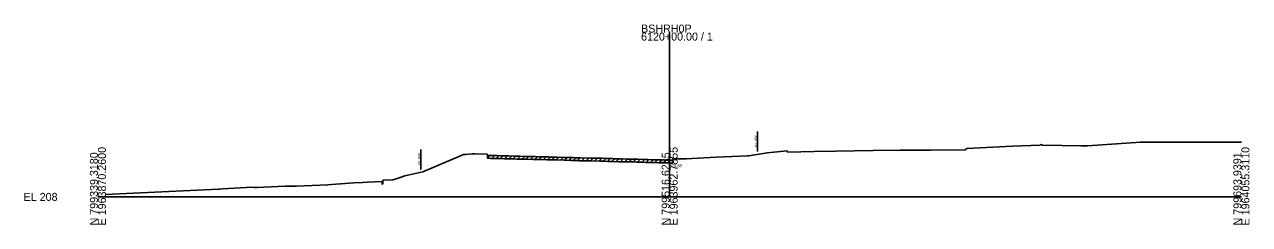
# Model space of a CAD drawing. Extents: x -26 to 1986619, y -10 to 827846.
# Drawn here: x -25.7 to 402.8, y -9.7 to 60.4 of the extents above; entities that cross this region are included whole.
import ezdxf

# ---------------------------------------------------------------- set-up
doc = ezdxf.new("R2010")
doc.units = 0
for name, color, linetype in [('Default', 7, 'Continuous'), ('RD_EX_Road', 7, 'Continuous'), ('RD_PD_ALT5_LnLine', 7, 'Continuous'), ('RD_PD_ALT5_TrvlWay', 7, 'Continuous'), ('RD_PD_PaveDit', 7, 'Continuous'), ('RD_XS_ExRW', 7, 'Continuous')]:
    doc.layers.add(name, color=color, linetype=linetype)

msp = doc.modelspace()

# ---------------------------------------------------------------- linework, layer by layer
at = {"layer": 'RD_EX_Road'}
for p, q in [((200, 0), (200, 57.54)), ((0, 0), (200, 0)), ((200, 0), (400, 0))]:
    msp.add_line(p, q, dxfattribs=at)
at = {"layer": 'RD_PD_ALT5_LnLine'}
msp.add_lwpolyline([(2.52, 0.85), (42.14, 2.71), (42.52, 2.72), (43.56, 2.78), (53.9, 3.34), (54.82, 3.33), (55.64, 3.31), (65.44, 3.69), (67.69, 3.75), (69.43, 3.8), (80.38, 4.27), (81.67, 4.35), (89.54, 4.92), (92.59, 5.07), (94.18, 5.17), (99.6, 5.39), (99.7, 5.84), (103.13, 6.02), (103.99, 6.19), (105.41, 6.7), (107.41, 7.31), (113.65, 8.78), (126.88, 14.39), (127.84, 14.8), (128.62, 14.88), (130.87, 15.1), (131.22, 15.12), (131.86, 15.11), (136.16, 14.95), (136.26, 14.5), (136.51, 14.5), (137.3, 14.48), (138.2, 14.46), (139.6, 14.43), (140.9, 14.39), (142.17, 14.36), (143.19, 14.33), (143.72, 14.32), (145.41, 14.28), (146.53, 14.25), (146.88, 14.24), (147.56, 14.23), (149.29, 14.19), (150.02, 14.16), (152.15, 14.1), (152.96, 14.08), (154.27, 14.05), (154.95, 14.03), (157.12, 13.98), (157.77, 13.97), (158.35, 13.96), (160.59, 13.92), (163.06, 13.83), (163.74, 13.81), (165.39, 13.76), (166.24, 13.73), (167.28, 13.7), (168.09, 13.69), (168.49, 13.67), (168.83, 13.67), (172.29, 13.6), (175.54, 13.53), (176.38, 13.5), (177.56, 13.45), (178.39, 13.42), (179.98, 13.38), (180.37, 13.37), (182.1, 13.32), (183.2, 13.3), (185.41, 13.25), (186.11, 13.24), (187.49, 13.24), (188.32, 13.21), (188.82, 13.2), (190.79, 13.12), (191.62, 13.09), (192.53, 13.07), (194.44, 13.01), (196.19, 12.96), (196.89, 12.94), (197.26, 12.93), (198.24, 12.91), (199.62, 12.88), (200.07, 12.88), (200.93, 12.8), (200.99, 12.9), (201.09, 13.35), (203.54, 13.35), (205.85, 13.33), (211.91, 13.67), (216.42, 13.88), (227.18, 14.32), (227.65, 14.34), (234.12, 15.4), (241.14, 16.12), (241.24, 15.67), (250.5, 15.93), (258.14, 16.01), (271.24, 16.26), (280.48, 16.39), (280.86, 16.39), (281.47, 16.36), (282.1, 16.36), (283.21, 16.36), (284.52, 16.34), (285.81, 16.3), (291.23, 16.37), (303.33, 16.5), (303.92, 16.96), (319.96, 17.81), (329.45, 18.1), (329.69, 18.33), (330.47, 18.13), (343.93, 17.86), (346.13, 17.93), (364.75, 19.12), (400, 19.18)], dxfattribs=at)
at = {"layer": 'RD_PD_PaveDit'}
for p, q in [((136.26, 13.5), (136.26, 14.5)), ((136.26, 13.5), (137.24, 14.49)), ((136.26, 13.5), (136.51, 13.5)), ((136.51, 13.5), (137.3, 13.48)), ((137.3, 13.48), (138.2, 13.46)), ((137.76, 13.47), (138.73, 14.45)), ((138.2, 13.46), (139.6, 13.43)), ((139.26, 13.43), (140.23, 14.41)), ((139.6, 13.43), (140.9, 13.39)), ((140.76, 13.39), (141.73, 14.37)), ((140.9, 13.39), (142.17, 13.36)), ((142.17, 13.36), (143.19, 13.33)), ((142.26, 13.35), (143.23, 14.33)), ((143.19, 13.33), (143.72, 13.32)), ((143.72, 13.32), (145.41, 13.28)), ((143.76, 13.32), (144.73, 14.29)), ((145.26, 13.28), (146.23, 14.26)), ((145.41, 13.28), (146.53, 13.25)), ((146.53, 13.25), (146.88, 13.24)), ((146.76, 13.25), (147.74, 14.22)), ((146.88, 13.24), (147.56, 13.23)), ((147.56, 13.23), (149.29, 13.19)), ((148.26, 13.21), (149.23, 14.19)), ((149.29, 13.19), (150.02, 13.16)), ((149.76, 13.17), (150.73, 14.14)), ((150.02, 13.16), (152.15, 13.1)), ((151.26, 13.13), (152.23, 14.1)), ((152.15, 13.1), (152.96, 13.08)), ((152.76, 13.09), (153.73, 14.06)), ((152.96, 13.08), (154.27, 13.05)), ((154.26, 13.05), (155.23, 14.02)), ((154.27, 13.05), (154.95, 13.03)), ((154.95, 13.03), (157.12, 12.98)), ((155.76, 13.01), (156.74, 13.99)), ((157.12, 12.98), (157.77, 12.97)), ((157.26, 12.98), (158.24, 13.96)), ((157.77, 12.97), (158.35, 12.96)), ((158.35, 12.96), (160.59, 12.92)), ((158.76, 12.95), (159.74, 13.94)), ((160.26, 12.93), (161.23, 13.9)), ((160.59, 12.92), (163.06, 12.83)), ((161.76, 12.88), (162.72, 13.84)), ((163.26, 12.82), (164.23, 13.79)), ((164.76, 12.78), (165.73, 13.74)), ((166.26, 12.73), (167.23, 13.71)), ((167.76, 12.69), (168.74, 13.67)), ((169.26, 12.67), (170.24, 13.64)), ((170.76, 12.63), (171.74, 13.61)), ((172.26, 12.6), (173.24, 13.58)), ((173.76, 12.57), (174.74, 13.55)), ((175.26, 12.54), (176.23, 13.51)), ((176.76, 12.49), (177.72, 13.44)), ((178.26, 12.42), (179.23, 13.4)), ((179.76, 12.38), (180.73, 13.36)), ((181.26, 12.34), (182.23, 13.32)), ((182.76, 12.31), (183.74, 13.29)), ((184.26, 12.28), (185.24, 13.26)), ((185.76, 12.25), (186.75, 13.24)), ((187.26, 12.24), (188.23, 13.22)), ((188.76, 12.2), (189.72, 13.16)), ((190.26, 12.14), (191.22, 13.11)), ((191.76, 12.09), (192.73, 13.06)), ((193.26, 12.04), (194.23, 13.01)), ((194.76, 12), (195.73, 12.97)), ((196.26, 11.96), (197.23, 12.93)), ((197.76, 11.92), (198.74, 12.9)), ((199.26, 11.89), (200.23, 12.86)), ((200.99, 13), (200.99, 12)), ((163.06, 12.83), (163.74, 12.81)), ((163.74, 12.81), (165.39, 12.76)), ((165.39, 12.76), (166.24, 12.73)), ((166.24, 12.73), (167.28, 12.7)), ((167.28, 12.7), (168.09, 12.69)), ((168.09, 12.69), (168.49, 12.67)), ((168.49, 12.67), (168.83, 12.67)), ((168.83, 12.67), (172.29, 12.6)), ((172.29, 12.6), (175.54, 12.53)), ((175.54, 12.53), (176.38, 12.5)), ((176.38, 12.5), (177.56, 12.45)), ((177.56, 12.45), (178.39, 12.42)), ((178.39, 12.42), (179.98, 12.38)), ((179.98, 12.38), (180.37, 12.37)), ((180.37, 12.37), (182.1, 12.32)), ((182.1, 12.32), (183.2, 12.3)), ((183.2, 12.3), (185.41, 12.25)), ((185.41, 12.25), (186.11, 12.24)), ((186.11, 12.24), (187.49, 12.24)), ((187.49, 12.24), (188.32, 12.21)), ((188.32, 12.21), (188.82, 12.2)), ((188.82, 12.2), (190.79, 12.12)), ((190.79, 12.12), (191.62, 12.09)), ((191.62, 12.09), (192.53, 12.07)), ((192.53, 12.07), (194.44, 12.01)), ((194.44, 12.01), (196.19, 11.96)), ((196.19, 11.96), (196.89, 11.94)), ((196.89, 11.94), (197.26, 11.93)), ((197.26, 11.93), (198.24, 11.91)), ((198.24, 11.91), (199.62, 11.88)), ((199.62, 11.88), (200.07, 11.88)), ((200.07, 11.88), (200.93, 11.8)), ((200.93, 11.8), (200.99, 12)), ((99.4, 4.38), (99.4, 5.38)), ((99.4, 4.38), (99.6, 4.39)), ((99.6, 4.39), (99.7, 4.84)), ((99.7, 5.84), (99.7, 4.84))]:
    msp.add_line(p, q, dxfattribs=at)
at = {"layer": 'RD_XS_ExRW'}
for p, q in [((230.68, 15.84), (230.68, 22.84)), ((113, 9.62), (113, 16.62))]:
    msp.add_line(p, q, dxfattribs=at)

# ---------------------------------------------------------------- texts
at = {"layer": 'Default'}
msp.add_text('-', height=0.0001, dxfattribs=at).set_placement((0, 0))
at = {"layer": 'RD_EX_Road'}
for s, p in [('BSHRH0P', (190, 57.54)), ('6120+00.00 / 1', (190, 54.74)), ('EL 208', (-26, -1.4))]:
    msp.add_text(s, height=2.8, dxfattribs=at).set_placement(p)
for s, p in [('E 1963870.2600', (2.8, -10)), ('E 1963962.7855', (202.8, -10)), ('E 1964055.3110', (402.8, -10)), ('N 799339.3180', (0, -10)), ('N 799516.6285', (200, -10)), ('N 799693.9391', (400, -10))]:
    msp.add_text(s, height=2.8, rotation=90, dxfattribs=at).set_placement(p)
at = {"layer": 'RD_PD_ALT5_TrvlWay'}
msp.add_text('220.88', height=1, dxfattribs=at).set_placement((200, 10.38))
at = {"layer": 'RD_XS_ExRW'}
for p in [(230.43, 17.51), (112.75, 11.3)]:
    msp.add_text('EX. R/W ', height=0.75, rotation=90, dxfattribs=at).set_placement(p)

doc.saveas('drawing.dxf')
